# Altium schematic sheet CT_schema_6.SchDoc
size 147 x 119 mm
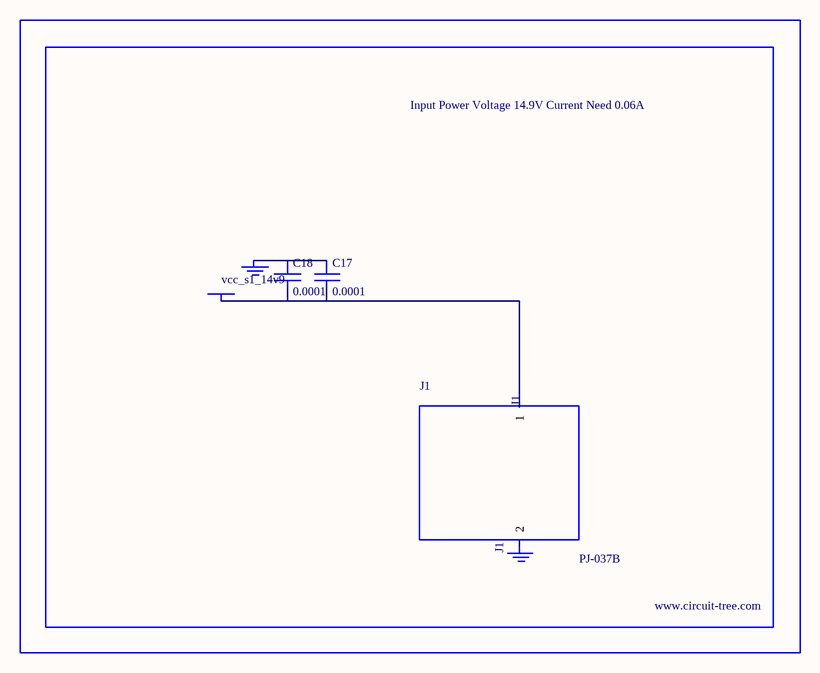
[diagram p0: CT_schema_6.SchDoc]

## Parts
BORDER5  (no value)
C17  0.0001  [EXV-9H]
C18  0.0001  [EXV-9H]
GND_INSTANCE_5_0  (no value)
GND_INSTANCE_5_1  (no value)
J1  PJ-037B  [PJ-037B_PACKAGE]
POWER_INSTANCE_5_0  vcc_s1_14v9

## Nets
NetC17_1: C17.1 C18.1 GND_INSTANCE_5_0.0(GND)
NetC17_2: C17.2 C18.2 J1.1 POWER_INSTANCE_5_0.0(PWR)

Not connected (* = marked no-connect by the designer): GND_INSTANCE_5_1 0(GND); J1 2

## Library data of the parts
BORDER5 = BORDER_PAGE5
C17 C18 = EDK107M035A9HAA
GND_INSTANCE_5_0 GND_INSTANCE_5_1 = GND
POWER_INSTANCE_5_0 = PWR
